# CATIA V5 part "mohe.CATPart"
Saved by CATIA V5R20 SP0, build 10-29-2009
Part number: mohe
Material "无"
Bounding box of the stored display mesh (mm): x 67.706 to 124.426, y -45.128 to 12.469, z -113.061 to 73.902
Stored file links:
  C:\Users\Administrator\Desktop\mohe.CATPart
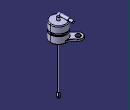
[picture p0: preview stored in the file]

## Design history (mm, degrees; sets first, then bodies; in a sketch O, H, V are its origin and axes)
Body1 (main body), material "无"
  DatumSurface1
  DatumCurve1
  Sketch1 on face of DatumSurface1, origin (102.3595, 0, 0), H (0, 1, 0), V (0, 0, 1)
    projected circle E1 centre (-24.7747, -110.5426) radius 1.5283 from edge of DatumCurve1
    arc A1 centre (-24.7747, -110.5426) radius 2.6386 from (-27.4132, -110.5706) to (-22.1362, -110.5146) ccw
    point P1 (-24.7747, -110.5426)
    point P2 (-27.4132, -110.5706)
    line L1 (-27.4132, -110.5706) -> (-27.5196, -100.5397)
    line L2 (-27.5196, -100.5397) -> (-22.2421, -100.5397)
    line L3 (-22.2421, -100.5397) -> (-22.1362, -110.5146)
    point P5 (-27.4132, -110.5706)
    concentricity: P1 E1
    coincidence: P2 A1, L1 P5, P2 P5
    tangency: L1 A1, L3 A1
    horizontal: L2 H
    parallelism: L1 L3
  Pad1: profile Sketch1, direction (1, 0, 0), length 3.5
  Fillet1: radius 0.2, on end face of Pad1; start face of Pad1
  DatumSurface2
  Sketch2 on face of Pad1 from Sketch1.L2, origin (0, 0, -100.5397), H (1, 0, 0), V (0, 1, 0)
    circle A1 centre (104.0425, -24.7447) radius 1.7172
  Pad2: profile Sketch2, direction (0, 0, 1), length 140
  Sketch3 on face of DatumSurface2, origin (0, 0, 17.2812), H (1, 0, 0), V (0, 1, 0)
    circle A1 centre (78.9825, -0.2306) radius 11.2763
    circle A2 centre (78.9825, -0.2306) radius 5.6349
  Pad3: profile Sketch3, direction (0, 0, 1), length 5
  Sketch4 on DatumSurface2, origin (0, 0, 17.2812), H (1, 0, 0), V (0, -1, 0)
    circle A1 centre (104.0425, 24.7447) radius 20.3837
    point P1 (104.0425, 24.7447)
    reference projected circle E1 centre (104.0425, 24.7447) radius 1.7172 from edge [face of Pad2 from Sketch2.A1 | end face of Pad2]
    circle A2 centre (104.0425, 24.7447) radius 2.2592
    concentricity: P1 E1
  Pad4: profile Sketch4, direction (0, 0, 1), length 40
  Plane1: type Offset, RefPlane end face of Pad4, Offset -20, reversed
  Sketch5 on Plane1, origin (0, 0, 37.2812), H (1, 0, 0), V (0, -1, 0)
    circle A1 centre (104.0425, 24.7447) radius 17.5384
    reference projected circle E1 centre (104.0425, 24.7447) radius 20.3837 from edge [face of Pad4 from Sketch4.A1 | start face of Pad4]
    concentricity: A1 E1
  Pocket1: profile Sketch5, direction (0, 0, 1), length 2, mirrored extent, outer side
  Fillet2: radius 1, on edge [start face of Pocket1 | face of Pad4 from Sketch4.A1]; edge [face of Pad4 from Sketch4.A1 | end face of Pocket1]
  Fillet3: radius 2, on edge [end face of Pad4 | face of Pad4 from Sketch4.A1]
  Sketch6 on DatumSurface2, origin (0, 0, 17.2812), H (1, 0, 0), V (0, -1, 0)
    projected circle E1 centre (78.9825, 0.2306) radius 11.2763 from edge [face of Pad3 from Sketch3.A1 | end face of Pad3]
    projected arc E2 centre (78.9825, 0.2306) radius 11.2763 from (88.1073, -6.3945) to (73.2733, 9.9548) ccw from edge [face of Pad3 from Sketch3.A1 | end face of Pad3]
    projected circle E3 centre (104.0425, 24.7447) radius 20.3837 from edge [face of Fillet3 | face of Pad4 from Sketch4.A1]
    projected arc E4 centre (104.0425, 24.7447) radius 20.3837 from (83.7358, 26.5155) to (106.5762, 4.519) ccw from edge [face of Fillet3 | face of Pad4 from Sketch4.A1]
    arc A1 centre (109.9281, -22.2376) radius 26.9658 from (88.1073, -6.3945) to (106.5762, 4.519) cw
    point P1 (88.1073, -6.3945)
    point P2 (106.5762, 4.519)
    arc A2 centre (62.4613, 28.3707) radius 21.3553 from (83.7358, 26.5155) to (73.2733, 9.9548) cw
    point P4 (83.7358, 26.5155)
    point P5 (73.2733, 9.9548)
    radius A1 = 26.9658
    radius A2 = 21.3553
    coincidence: E1 P1, E3 P2, E3 P4, E1 P5
    tangency: A1 E1, A1 E3, A2 E3, A2 E1
  Pad5: profile Sketch6, direction (0, 0, 1), up to end face of Pad3
  Fillet4: radius 0.5, on face of Pad3
  Fillet5: radius 0.5, on face of Pad4
  Sketch7 on end face of Pad4, origin (0, 0, 57.2812), H (1, 0, 0), V (0, 1, 0)
    point P1 (104.0425, -24.7447)
    reference projected circle E1 centre (104.0425, -24.7447) radius 18.3837 from edge [end face of Pad4 | face of Fillet3]
    concentricity: E1 P1
  Plane2: type OffsetPt, RefPlane yz-plane, RefPoint Sketch7
  Sketch8 on Plane2, origin (104.0425, 0, 0), H (0, 1, 0), V (0, 0, 1)
    line L1 (-24.7376, 56.9064) -> (-24.7376, 64.6779)
    line L2 (-19.2862, 70.1293) -> (12.469, 70.1293)
    arc A1 centre (-19.2862, 64.6779) radius 5.4514 from (-19.2862, 70.1293) to (-24.7376, 64.6779) ccw
    radius A1 = 5.4514
    vertical: L1 V
    horizontal: L2 H
    tangency: A1 L2, A1 L1
  Sweep1: type Unspec, Profile edge [face of Pad4 from Sketch4.A2 | end face of Pad4], Guide Sketch8
  ThickSurface1: Surface Sweep1, TopOffset 1.7, BotOffset 0
  Sketch9 on face of ThickSurface1, origin (0, 12.469, 0), H (-1, 0, 0), V (0, 0, 1)
    circle A1 centre (-104.0425, 70.1363) radius 3.0358
    reference projected circle E1 centre (-104.0425, 70.1363) radius 2.2592 from edge [face of ThickSurface1 | face of ThickSurface1]
    circle A2 centre (-104.0425, 70.1363) radius 9.1111
    concentricity: A1 E1
  Pocket2: profile Sketch9, direction (0, -1, 0), length 10
  Fillet6: radius 0.2, on edge [face of ThickSurface1 | end face of Pocket2]; edge [end face of Pocket2 | face of Pocket2 from Sketch9.A1]; edge [face of Pocket2 from Sketch9.A1 | face of ThickSurface1]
